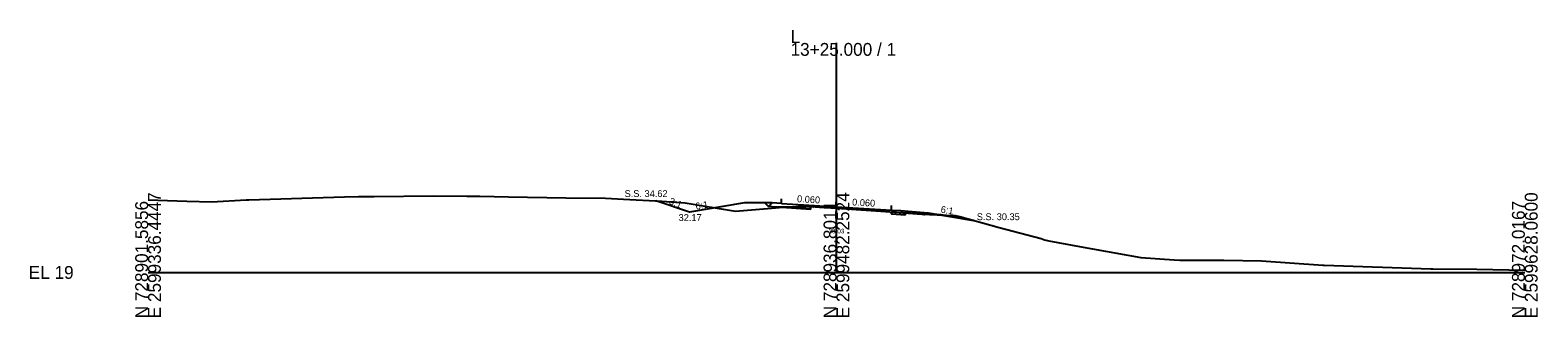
# Model space of a CAD drawing. Extents: x -26 to 3303, y -10 to 9555.
# Drawn here: x -25.7 to 302.8, y 6490.3 to 6552.9 of the extents above; entities that cross this region are included whole.
import ezdxf

# ---------------------------------------------------------------- set-up
doc = ezdxf.new("R2010")
doc.units = 0
for name, color, linetype in [('Exist Cross Section Cell', 7, 'Continuous'), ('Exist XS Center Line Elevation Label', 7, 'Continuous'), ('Exist XS Ground Line', 7, 'Continuous'), ('Prop XS Ditch Slope Text', 7, 'Continuous'), ('Prop XS Ditch Standard Text', 7, 'Continuous'), ('Prop XS Dump Level', 7, 'Continuous'), ('Prop XS Earthwork Shape', 7, 'Continuous'), ('Prop XS EOT Tick Mark', 7, 'Continuous'), ('Prop XS Finish Grade', 7, 'Continuous'), ('Prop XS Finish Grade Earthwork', 7, 'Continuous'), ('Prop XS Finish Grade Paved Shoulder', 7, 'Continuous'), ('Prop XS Finish Grade Pavement', 7, 'Continuous'), ('Prop XS Pvmt Edge Slope', 7, 'Continuous'), ('Prop XS SE Text', 7, 'Continuous'), ('Prop XS Side Slope Text', 7, 'Continuous'), ('Prop XS SS Elevation Text', 7, 'Continuous'), ('Prop XS Subgrade Earthwork', 7, 'Continuous')]:
    doc.layers.add(name, color=color, linetype=linetype)

msp = doc.modelspace()

# ---------------------------------------------------------------- linework, layer by layer
at = {"layer": 'Exist Cross Section Cell'}
for p, q in [((150, 6500), (150, 6550.07)), ((0, 6500), (150, 6500)), ((150, 6500), (300, 6500))]:
    msp.add_line(p, q, dxfattribs=at)
at = {"layer": 'Exist XS Ground Line'}
msp.add_lwpolyline([(0, 6515.85), (8.44, 6515.56), (13.86, 6515.4), (21.36, 6515.83), (21.98, 6515.86), (42.8, 6516.48), (45.88, 6516.56), (49.24, 6516.57), (62.09, 6516.69), (69.46, 6516.65), (72.32, 6516.62), (78.52, 6516.52), (91.07, 6516.27), (99.66, 6516.21), (103.57, 6516.01), (111.98, 6515.54), (117.01, 6515.2), (127.97, 6513.34), (136.74, 6514.07), (138.32, 6514.23), (143.95, 6514.39), (144.37, 6514.4), (147.36, 6514.2), (148.75, 6514.11), (150, 6514.03), (156.49, 6513.59), (159.66, 6513.34), (168.6, 6512.69), (175.21, 6512.45), (175.86, 6512.42), (176.87, 6512.19), (185.44, 6509.84), (194.62, 6507.4), (195.31, 6507.15), (196.29, 6506.91), (202.95, 6505.69), (216.33, 6503.24), (223.58, 6502.73), (224.82, 6502.69), (234.45, 6502.7), (242.6, 6502.52), (256, 6501.6), (256.31, 6501.6), (279.52, 6500.79), (279.94, 6500.78), (289.55, 6500.75), (300, 6500.52)], dxfattribs=at)
at = {"layer": 'Prop XS Dump Level'}
for p, q in [((138, 6515.05), (150, 6514.33)), ((150, 6514.33), (162, 6513.61))]:
    msp.add_line(p, q, dxfattribs=at)
at = {"layer": 'Prop XS Earthwork Shape'}
for points in [[(118, 6513.17), (110.65, 6515.62), (111.98, 6515.54), (117.01, 6515.2), (123.54, 6514.09)], [(118, 6513.17), (110.65, 6515.62), (111.98, 6515.54), (117.01, 6515.2), (123.54, 6514.09)], [(125.28, 6514.38), (123.54, 6514.09), (127.97, 6513.34), (136.74, 6514.07), (138.13, 6514.21), (138, 6514.21), (136, 6514.33), (135.21, 6514.38), (134.43, 6515.17), (130, 6515.17)], [(125.28, 6514.38), (123.54, 6514.09), (127.97, 6513.34), (136.74, 6514.07), (138.13, 6514.21), (138, 6514.21), (136, 6514.33), (135.21, 6514.38), (134.43, 6515.17), (130, 6515.17)], [(138.13, 6514.21), (138.32, 6514.23), (143.95, 6514.39), (144.37, 6514.4), (144.37, 6513.83)], [(144.37, 6513.83), (144.37, 6514.4), (143.95, 6514.39), (138.32, 6514.23), (138.13, 6514.21)], [(164, 6512.65), (164.89, 6512.6), (165.22, 6512.94), (162, 6513.17), (162, 6512.77)], [(164, 6512.65), (164.89, 6512.6), (165.22, 6512.94), (162, 6513.17), (162, 6512.77)], [(170, 6513.01), (172.82, 6512.54), (168.6, 6512.69), (165.22, 6512.94), (165.64, 6513.36)], [(170, 6513.01), (172.82, 6512.54), (168.6, 6512.69), (165.22, 6512.94), (165.64, 6513.36)], [(172.82, 6512.54), (175.21, 6512.45), (175.86, 6512.42), (176.87, 6512.19), (179.93, 6511.35), (179.41, 6511.44)], [(172.82, 6512.54), (175.21, 6512.45), (175.86, 6512.42), (176.87, 6512.19), (179.93, 6511.35), (179.41, 6511.44)]]:
    msp.add_lwpolyline(points, close=True, dxfattribs=at)
at = {"layer": 'Prop XS EOT Tick Mark'}
for p, q in [((138, 6515.05), (138, 6516.05)), ((162, 6513.61), (162, 6514.61))]:
    msp.add_line(p, q, dxfattribs=at)
at = {"layer": 'Prop XS Finish Grade'}
for p, q in [((136, 6515.17), (134.43, 6515.17)), ((164, 6513.49), (165.64, 6513.36))]:
    msp.add_line(p, q, dxfattribs=at)
at = {"layer": 'Prop XS Finish Grade Earthwork'}
for p, q in [((118, 6513.17), (110.65, 6515.62)), ((130, 6515.17), (125.28, 6514.38)), ((134.43, 6515.17), (130, 6515.17)), ((125.28, 6514.38), (118, 6513.17)), ((165.64, 6513.36), (170, 6513.01)), ((170, 6513.01), (179.41, 6511.44)), ((179.41, 6511.44), (179.93, 6511.35))]:
    msp.add_line(p, q, dxfattribs=at)
at = {"layer": 'Prop XS Finish Grade Paved Shoulder'}
for p, q in [((138, 6515.05), (136, 6515.17)), ((162, 6513.61), (164, 6513.49))]:
    msp.add_line(p, q, dxfattribs=at)
at = {"layer": 'Prop XS Finish Grade Pavement'}
for p, q in [((138, 6515.05), (150, 6514.33)), ((150, 6514.33), (162, 6513.61))]:
    msp.add_line(p, q, dxfattribs=at)
at = {"layer": 'Prop XS Pvmt Edge Slope'}
for p, q in [((135.21, 6514.38), (134.43, 6515.17)), ((136, 6515.17), (135.21, 6514.38)), ((164, 6513.49), (164.89, 6512.6)), ((164.89, 6512.6), (165.64, 6513.36))]:
    msp.add_line(p, q, dxfattribs=at)
at = {"layer": 'Prop XS Subgrade Earthwork'}
for p, q in [((135.21, 6514.38), (134.43, 6515.17)), ((136, 6514.33), (135.21, 6514.38)), ((138, 6514.21), (136, 6514.33)), ((144.37, 6513.83), (138, 6514.21)), ((144.37, 6513.83), (144.37, 6514.4)), ((162, 6512.77), (162, 6513.17)), ((162, 6512.77), (164, 6512.65)), ((164, 6512.65), (164.89, 6512.6)), ((164.89, 6512.6), (165.64, 6513.36))]:
    msp.add_line(p, q, dxfattribs=at)

# ---------------------------------------------------------------- texts
at = {"layer": 'Exist Cross Section Cell'}
for s, p in [('L', (140, 6550.07)), ('13+25.000 / 1', (140, 6547.27)), ('EL 19', (-26, 6498.6))]:
    msp.add_text(s, height=2.8, dxfattribs=at).set_placement(p)
for s, p in [('N 728901.5856', (0, 6490)), ('E 2599336.4447', (2.8, 6490)), ('N 728936.8011', (150, 6490)), ('E 2599482.2524', (152.8, 6490)), ('N 728972.0167', (300, 6490)), ('E 2599628.0600', (302.8, 6490))]:
    msp.add_text(s, height=2.8, rotation=90, dxfattribs=at).set_placement(p)
at = {"layer": 'Exist XS Center Line Elevation Label'}
msp.add_text('33.03', height=1, dxfattribs=at).set_placement((148.27, 6508.53))
at = {"layer": 'Prop XS Ditch Slope Text'}
for rotation, p in [(9.4623, (119.42, 6513.68)), (350.5377, (172.63, 6513.07))]:
    msp.add_text('6:1', height=1.5, rotation=rotation, dxfattribs=at).set_placement(p)
at = {"layer": 'Prop XS Ditch Standard Text'}
msp.add_text('32.17', height=1.5, dxfattribs=at).set_placement((115.61, 6511.22))
at = {"layer": 'Prop XS Dump Level'}
for s, height, p in [('Case1', 0.04, (130, 6515.13)), ('Eop', 0.3, (144.37, 6514.1)), ('Eop', 0.3, (168.6, 6512.39)), ('Case1', 0.04, (170, 6512.97))]:
    msp.add_text(s, height=height, dxfattribs=at).set_placement(p)
at = {"layer": 'Prop XS SE Text'}
for p in [(141.38, 6515.35), (153.38, 6514.63)]:
    msp.add_text('0.060', height=1.5, rotation=356.5664, dxfattribs=at).set_placement(p)
at = {"layer": 'Prop XS Side Slope Text'}
msp.add_text('3:1', height=1.5, rotation=338.321, dxfattribs=at).set_placement((113.38, 6514.99))
at = {"layer": 'Prop XS SS Elevation Text'}
for s, p in [('S.S. 34.62', (103.84, 6516.45)), ('S.S. 30.35', (180.58, 6511.41))]:
    msp.add_text(s, height=1.5, dxfattribs=at).set_placement(p)

doc.saveas('drawing.dxf')
